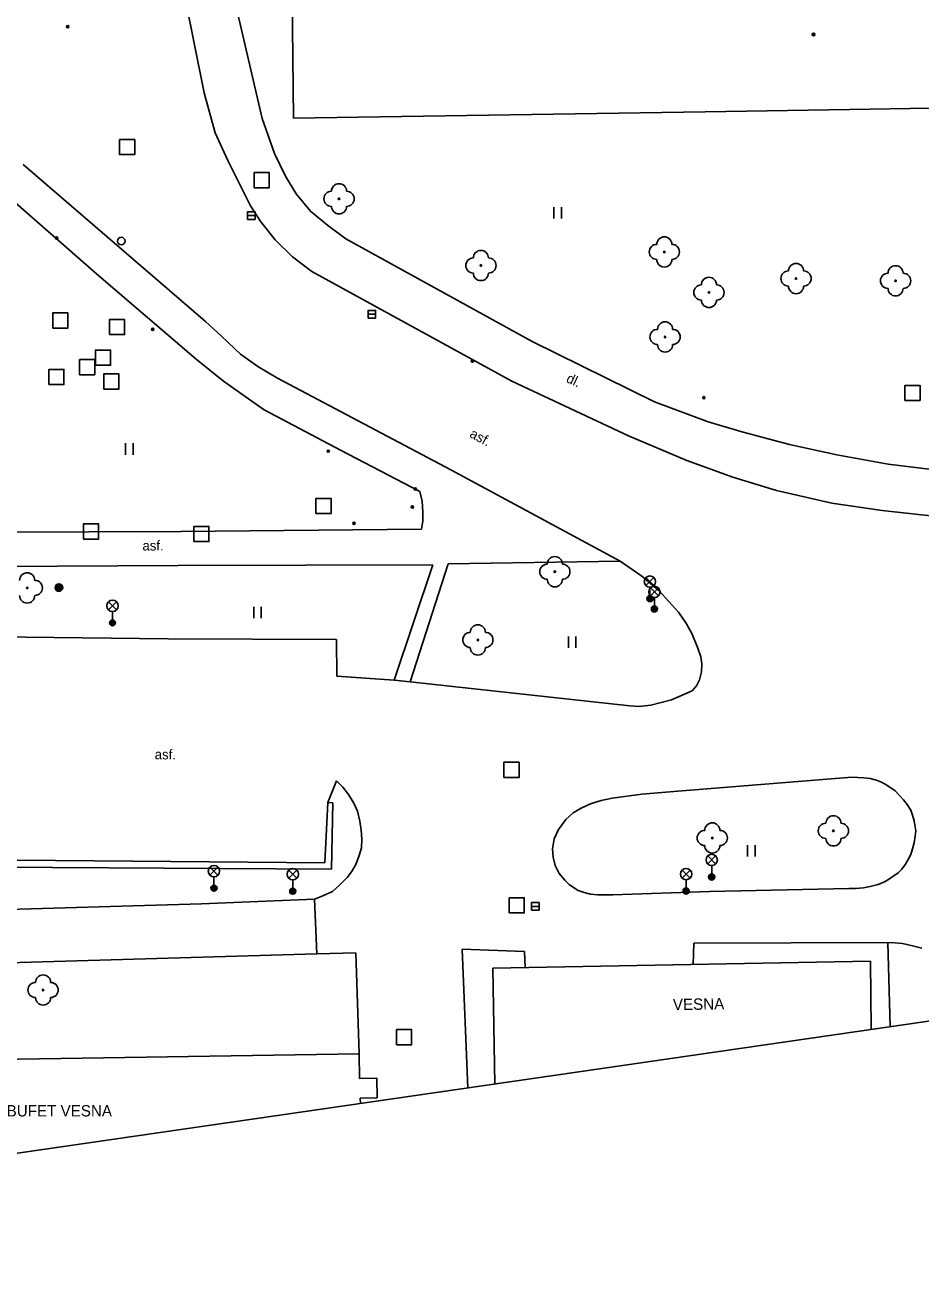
# Model space of a CAD drawing. Extents: x -641829 to -641525, y -1114855 to -1114359.
# Drawn here: x -641632.1 to -641572.8, y -1114854.7 to -1114772 of the extents above; entities that cross this region are included whole.
import ezdxf

# ---------------------------------------------------------------- set-up
doc = ezdxf.new("R2010")
doc.units = 0
for name, color, linetype in [('Vrstva 1', 7, 'Continuous'), ('Vrstva 10', 7, 'Continuous'), ('Vrstva 11', 7, 'Continuous'), ('Vrstva 20', 7, 'Continuous'), ('Vrstva 22', 7, 'Continuous'), ('Vrstva 25', 7, 'Continuous'), ('Vrstva 26', 7, 'Continuous'), ('Vrstva 27', 7, 'Continuous'), ('Vrstva 28', 7, 'Continuous'), ('Vrstva 33', 7, 'Continuous'), ('Vrstva 36', 7, 'Continuous'), ('Vrstva 39', 7, 'Continuous'), ('Vrstva 40', 7, 'Continuous'), ('Vrstva 41', 7, 'Continuous'), ('Vrstva 5', 7, 'Continuous')]:
    doc.layers.add(name, color=color, linetype=linetype)

msp = doc.modelspace()

# ---------------------------------------------------------------- linework, layer by layer
at = {"layer": 'Vrstva 1'}
msp.add_line((-641689.21, -1114854.71), (-641533.66, -1114832.21), dxfattribs=at)
at = {"layer": 'Vrstva 10'}
for p, q in [((-641621.81, -1114768.5), (-641620.22, -1114776.44)), ((-641620.22, -1114776.44), (-641619.48, -1114779.08)), ((-641619.48, -1114779.08), (-641618.65, -1114780.9)), ((-641632.18, -1114781.17), (-641620.12, -1114791.56)), ((-641618.65, -1114780.9), (-641617.15, -1114783.91)), ((-641617.15, -1114783.91), (-641616.47, -1114784.97)), ((-641616.47, -1114784.97), (-641615.51, -1114786.15)), ((-641615.51, -1114786.15), (-641614.36, -1114787.27)), ((-641614.36, -1114787.27), (-641613.09, -1114788.24)), ((-641613.09, -1114788.24), (-641599.87, -1114795.5)), ((-641620.12, -1114791.56), (-641619.04, -1114792.55)), ((-641619.04, -1114792.55), (-641617.81, -1114793.71)), ((-641617.81, -1114793.71), (-641616.66, -1114794.53)), ((-641616.66, -1114794.53), (-641615.36, -1114795.29)), ((-641603.9, -1114801.36), (-641615.36, -1114795.29)), ((-641599.87, -1114795.5), (-641592.15, -1114799.11)), ((-641592.15, -1114799.11), (-641588.29, -1114800.74)), ((-641592.71, -1114807.4), (-641603.9, -1114801.36)), ((-641588.29, -1114800.74), (-641585.25, -1114801.84)), ((-641585.25, -1114801.84), (-641582.37, -1114802.73)), ((-641582.37, -1114802.73), (-641578.7, -1114803.55)), ((-641578.7, -1114803.55), (-641575.38, -1114804.04)), ((-641575.38, -1114804.04), (-641571.75, -1114804.44)), ((-641591.27, -1114808.39), (-641592.71, -1114807.4)), ((-641590.12, -1114809.36), (-641591.27, -1114808.39)), ((-641588.84, -1114810.76), (-641590.12, -1114809.36)), ((-641588.32, -1114811.54), (-641588.84, -1114810.76)), ((-641587.93, -1114812.22), (-641588.32, -1114811.54)), ((-641637.17, -1114812.37), (-641622.59, -1114812.52)), ((-641622.59, -1114812.52), (-641611.46, -1114812.58)), ((-641611.46, -1114812.58), (-641611.44, -1114814.99)), ((-641587.56, -1114813.15), (-641587.93, -1114812.22)), ((-641587.37, -1114813.71), (-641587.56, -1114813.15)), ((-641587.29, -1114814.19), (-641587.37, -1114813.71)), ((-641587.33, -1114814.71), (-641587.29, -1114814.19)), ((-641607.65, -1114815.27), (-641611.44, -1114814.99)), ((-641607.65, -1114815.27), (-641606.58, -1114815.36)), ((-641606.58, -1114815.36), (-641592.07, -1114816.96)), ((-641587.66, -1114815.64), (-641587.45, -1114815.23)), ((-641587.45, -1114815.23), (-641587.33, -1114814.71)), ((-641589.31, -1114816.55), (-641587.95, -1114815.96)), ((-641587.95, -1114815.96), (-641587.66, -1114815.64)), ((-641592.07, -1114816.96), (-641591.46, -1114816.99)), ((-641591.46, -1114816.99), (-641590.67, -1114816.91)), ((-641590.67, -1114816.91), (-641589.99, -1114816.74)), ((-641589.99, -1114816.74), (-641589.31, -1114816.55)), ((-641612.04, -1114823.35), (-641611.45, -1114821.91)), ((-641611.45, -1114821.91), (-641611.05, -1114822.34)), ((-641589.15, -1114822.62), (-641577.38, -1114821.68)), ((-641577.38, -1114821.68), (-641576.58, -1114821.71)), ((-641576.58, -1114821.71), (-641576.16, -1114821.77)), ((-641576.16, -1114821.77), (-641575.76, -1114821.87)), ((-641575.76, -1114821.87), (-641575.41, -1114822.01)), ((-641575.41, -1114822.01), (-641575.06, -1114822.19)), ((-641611.05, -1114822.34), (-641610.66, -1114822.82)), ((-641610.66, -1114822.82), (-641610.31, -1114823.4)), ((-641593.24, -1114823.05), (-641591.27, -1114822.79)), ((-641591.27, -1114822.79), (-641589.15, -1114822.62)), ((-641575.06, -1114822.19), (-641574.51, -1114822.58)), ((-641574.51, -1114822.58), (-641573.97, -1114823.18)), ((-641610.31, -1114823.4), (-641610.08, -1114823.92)), ((-641595.81, -1114824.02), (-641595.28, -1114823.72)), ((-641595.28, -1114823.72), (-641594.66, -1114823.44)), ((-641594.66, -1114823.44), (-641593.96, -1114823.22)), ((-641593.96, -1114823.22), (-641593.24, -1114823.05)), ((-641573.97, -1114823.18), (-641573.72, -1114823.48)), ((-641573.72, -1114823.48), (-641573.49, -1114823.86)), ((-641610.08, -1114823.92), (-641609.91, -1114824.59)), ((-641609.91, -1114824.59), (-641609.83, -1114825.17)), ((-641596.78, -1114825.13), (-641596.29, -1114824.48)), ((-641596.29, -1114824.48), (-641595.81, -1114824.02)), ((-641573.49, -1114823.86), (-641573.36, -1114824.19)), ((-641573.36, -1114824.19), (-641573.25, -1114824.56)), ((-641573.25, -1114824.56), (-641573.16, -1114825.23)), ((-641609.83, -1114825.17), (-641609.79, -1114825.77)), ((-641597.06, -1114825.75), (-641596.78, -1114825.13)), ((-641573.16, -1114825.23), (-641573.19, -1114825.58)), ((-641609.79, -1114825.77), (-641609.81, -1114826.34)), ((-641597.18, -1114826.41), (-641597.06, -1114825.75)), ((-641573.26, -1114826.01), (-641573.36, -1114826.41)), ((-641573.19, -1114825.58), (-641573.26, -1114826.01)), ((-641609.95, -1114826.85), (-641610.18, -1114827.44)), ((-641609.81, -1114826.34), (-641609.95, -1114826.85)), ((-641597.18, -1114826.41), (-641597.13, -1114826.95)), ((-641597.13, -1114826.95), (-641596.99, -1114827.51)), ((-641573.64, -1114827.07), (-641573.84, -1114827.42)), ((-641573.49, -1114826.78), (-641573.64, -1114827.07)), ((-641573.36, -1114826.41), (-641573.49, -1114826.78)), ((-641610.47, -1114827.92), (-641610.76, -1114828.31)), ((-641610.18, -1114827.44), (-641610.47, -1114827.92)), ((-641596.99, -1114827.51), (-641596.74, -1114828.03)), ((-641574.08, -1114827.75), (-641574.32, -1114827.99)), ((-641573.84, -1114827.42), (-641574.08, -1114827.75)), ((-641610.76, -1114828.31), (-641611.25, -1114828.82)), ((-641596.74, -1114828.03), (-641596.36, -1114828.49)), ((-641596.07, -1114828.76), (-641596.36, -1114828.49)), ((-641595.78, -1114828.97), (-641596.07, -1114828.76)), ((-641575.23, -1114828.59), (-641575.65, -1114828.77)), ((-641574.9, -1114828.4), (-641575.23, -1114828.59)), ((-641574.32, -1114827.99), (-641574.9, -1114828.4)), ((-641612.36, -1114829.52), (-641612.91, -1114829.73)), ((-641611.72, -1114829.22), (-641612.36, -1114829.52)), ((-641611.25, -1114828.82), (-641611.72, -1114829.22)), ((-641595.47, -1114829.16), (-641595.78, -1114828.97)), ((-641595.09, -1114829.3), (-641595.47, -1114829.16)), ((-641594.66, -1114829.41), (-641595.09, -1114829.3)), ((-641594.2, -1114829.45), (-641594.66, -1114829.41)), ((-641593.18, -1114829.46), (-641594.2, -1114829.45)), ((-641586.77, -1114829.24), (-641593.18, -1114829.46)), ((-641577.59, -1114829.04), (-641586.77, -1114829.24)), ((-641577.14, -1114829.03), (-641577.59, -1114829.04)), ((-641576.62, -1114828.98), (-641577.14, -1114829.03)), ((-641576.16, -1114828.9), (-641576.62, -1114828.98)), ((-641575.65, -1114828.77), (-641576.16, -1114828.9)), ((-641612.75, -1114833.36), (-641612.91, -1114829.73)), ((-641575.01, -1114832.61), (-641574.54, -1114832.62)), ((-641574.54, -1114832.62), (-641574.03, -1114832.67)), ((-641574.03, -1114832.67), (-641573.38, -1114832.81)), ((-641573.38, -1114832.81), (-641572.75, -1114832.98)), ((-641612.75, -1114833.36), (-641610.17, -1114833.29)), ((-641610.17, -1114833.29), (-641609.97, -1114839.96)), ((-641602.782, -1114842.208), (-641603.14, -1114833.04)), ((-641603.14, -1114833.04), (-641599.03, -1114833.19)), ((-641599.03, -1114833.19), (-641598.99, -1114834.26))]:
    msp.add_line(p, q, dxfattribs=at)
at = {"layer": 'Vrstva 11'}
for p, q in [((-641616.38, -1114778.12), (-641618.71, -1114768.03)), ((-641615.55, -1114780.44), (-641616.38, -1114778.12)), ((-641614.83, -1114781.94), (-641615.55, -1114780.44)), ((-641634.75, -1114781.92), (-641627.17, -1114788.53)), ((-641614.13, -1114783.1), (-641614.83, -1114781.94)), ((-641613.17, -1114784.25), (-641614.13, -1114783.1)), ((-641612.06, -1114785.18), (-641613.17, -1114784.25)), ((-641610.84, -1114786.08), (-641612.06, -1114785.18)), ((-641598.52, -1114792.88), (-641610.84, -1114786.08)), ((-641627.17, -1114788.53), (-641620.73, -1114794.04)), ((-641590.42, -1114796.87), (-641598.52, -1114792.88)), ((-641620.73, -1114794.04), (-641618.92, -1114795.5)), ((-641618.92, -1114795.5), (-641617.5, -1114796.51)), ((-641617.5, -1114796.51), (-641616.24, -1114797.4)), ((-641586.89, -1114798.18), (-641590.42, -1114796.87)), ((-641616.24, -1114797.4), (-641611.19, -1114800.05)), ((-641584.57, -1114798.87), (-641586.89, -1114798.18)), ((-641581.5, -1114799.67), (-641584.57, -1114798.87)), ((-641578.37, -1114800.36), (-641581.5, -1114799.67)), ((-641611.19, -1114800.05), (-641605.95, -1114802.79)), ((-641574.98, -1114800.99), (-641578.37, -1114800.36)), ((-641571.18, -1114801.45), (-641574.98, -1114800.99)), ((-641605.95, -1114802.79), (-641605.79, -1114803.43)), ((-641605.79, -1114803.43), (-641605.74, -1114804.15)), ((-641605.76, -1114804.75), (-641605.83, -1114805.28)), ((-641605.74, -1114804.15), (-641605.76, -1114804.75)), ((-641621.75, -1114805.43), (-641634.53, -1114805.48)), ((-641605.83, -1114805.28), (-641621.75, -1114805.43)), ((-641621.92, -1114807.67), (-641634.02, -1114807.75)), ((-641605.09, -1114807.63), (-641621.92, -1114807.67)), ((-641607.65, -1114815.27), (-641605.09, -1114807.63)), ((-641604.08, -1114807.57), (-641606.58, -1114815.36)), ((-641604.08, -1114807.57), (-641592.71, -1114807.4)), ((-641612.23, -1114827.33), (-641612.04, -1114823.35)), ((-641612.04, -1114823.35), (-641611.71, -1114823.36)), ((-641611.8, -1114827.76), (-641611.71, -1114823.36)), ((-641637.68, -1114827.61), (-641611.8, -1114827.76)), ((-641637.5, -1114830.54), (-641620.39, -1114830.05)), ((-641620.39, -1114830.05), (-641612.91, -1114829.73)), ((-641587.84, -1114832.65), (-641587.88, -1114834.06)), ((-641575.01, -1114832.61), (-641587.84, -1114832.65)), ((-641574.846, -1114838.167), (-641575.01, -1114832.61)), ((-641612.75, -1114833.36), (-641634.7, -1114833.98))]:
    msp.add_line(p, q, dxfattribs=at)
msp.add_lwpolyline([(-641612.23, -1114827.33), (-641637.68, -1114827.12)], dxfattribs=at)
at = {"layer": 'Vrstva 20'}
for centre, radius in [((-641629.23, -1114772.06), 0.075), ((-641629.23, -1114772.06), 0.0204), ((-641629.97, -1114786.03), 0.075), ((-641629.97, -1114786.03), 0.0204), ((-641623.61, -1114792.07), 0.075), ((-641623.61, -1114792.07), 0.0204), ((-641602.47, -1114794.17), 0.075), ((-641602.47, -1114794.17), 0.0204), ((-641587.17, -1114796.58), 0.075), ((-641587.17, -1114796.58), 0.0204), ((-641612, -1114800.12), 0.075), ((-641612, -1114800.12), 0.0204), ((-641606.25, -1114802.62), 0.075), ((-641606.25, -1114802.62), 0.0204), ((-641606.44, -1114803.81), 0.075), ((-641606.44, -1114803.81), 0.0204), ((-641610.3, -1114804.89), 0.075), ((-641610.3, -1114804.89), 0.0204)]:
    msp.add_circle(centre, radius, dxfattribs=at)
at = {"layer": 'Vrstva 22'}
for centre in [(-641611.29, -1114783.44), (-641589.78, -1114786.95), (-641601.91, -1114787.85), (-641581.07, -1114788.71), (-641574.49, -1114788.86), (-641586.83, -1114789.63), (-641589.73, -1114792.57), (-641597.02, -1114808.09), (-641631.91, -1114809.16), (-641602.11, -1114812.6), (-641578.6, -1114825.22), (-641586.61, -1114825.69), (-641630.86, -1114835.74)]:
    msp.add_circle(centre, 0.05, dxfattribs=at)
for centre, start, end in [((-641611.79, -1114783.44), 90, 270), ((-641611.29, -1114782.94), 0, 180), ((-641610.79, -1114783.44), 270, 90), ((-641611.29, -1114783.94), 180, 0), ((-641590.28, -1114786.95), 90, 270), ((-641589.78, -1114786.45), 0, 180), ((-641589.28, -1114786.95), 270, 90), ((-641602.41, -1114787.85), 90, 270), ((-641601.91, -1114787.35), 0, 180), ((-641601.41, -1114787.85), 270, 90), ((-641589.78, -1114787.45), 180, 0), ((-641581.57, -1114788.71), 90, 270), ((-641581.07, -1114788.21), 0, 180), ((-641580.57, -1114788.71), 270, 90), ((-641574.49, -1114788.36), 0, 180), ((-641601.91, -1114788.35), 180, 0), ((-641586.83, -1114789.13), 0, 180), ((-641574.99, -1114788.86), 90, 270), ((-641573.99, -1114788.86), 270, 90), ((-641587.33, -1114789.63), 90, 270), ((-641586.33, -1114789.63), 270, 90), ((-641581.07, -1114789.21), 180, 0), ((-641574.49, -1114789.36), 180, 0), ((-641586.83, -1114790.13), 180, 0), ((-641590.23, -1114792.57), 90, 270), ((-641589.73, -1114792.07), 0, 180), ((-641589.23, -1114792.57), 270, 90), ((-641589.73, -1114793.07), 180, 0), ((-641597.02, -1114807.59), 0, 180), ((-641597.52, -1114808.09), 90, 270), ((-641596.52, -1114808.09), 270, 90), ((-641631.91, -1114808.66), 0, 180), ((-641631.41, -1114809.16), 270, 90), ((-641597.02, -1114808.59), 180, 0), ((-641631.91, -1114809.66), 180, 0), ((-641602.61, -1114812.6), 90, 270), ((-641602.11, -1114812.1), 0, 180), ((-641601.61, -1114812.6), 270, 90), ((-641602.11, -1114813.1), 180, 0), ((-641578.6, -1114824.72), 0, 180), ((-641587.11, -1114825.69), 90, 270), ((-641586.61, -1114825.19), 0, 180), ((-641586.11, -1114825.69), 270, 90), ((-641579.1, -1114825.22), 90, 270), ((-641578.1, -1114825.22), 270, 90), ((-641586.61, -1114826.19), 180, 0), ((-641578.6, -1114825.72), 180, 0), ((-641631.36, -1114835.74), 90, 270), ((-641630.86, -1114835.24), 0, 180), ((-641630.36, -1114835.74), 270, 90), ((-641630.86, -1114836.24), 180, 0)]:
    msp.add_arc(centre, 0.5, start, end, dxfattribs=at)
at = {"layer": 'Vrstva 25'}
for radius in [0.25, 0.2, 0.15, 0.1, 0.05]:
    msp.add_circle((-641629.81, -1114809.14), radius, dxfattribs=at)
at = {"layer": 'Vrstva 26'}
for points in [[(-641624.8, -1114779.52), (-641625.8, -1114779.52), (-641625.8, -1114780.52), (-641624.8, -1114780.52)], [(-641616.91, -1114782.71), (-641615.91, -1114782.71), (-641615.91, -1114781.71), (-641616.91, -1114781.71)], [(-641630.22, -1114791.98), (-641629.22, -1114791.98), (-641629.22, -1114790.98), (-641630.22, -1114790.98)], [(-641626.47, -1114792.42), (-641625.47, -1114792.42), (-641625.47, -1114791.42), (-641626.47, -1114791.42)], [(-641627.4, -1114794.44), (-641626.4, -1114794.44), (-641626.4, -1114793.44), (-641627.4, -1114793.44)], [(-641630.48, -1114795.72), (-641629.48, -1114795.72), (-641629.48, -1114794.72), (-641630.48, -1114794.72)], [(-641628.45, -1114795.07), (-641627.45, -1114795.07), (-641627.45, -1114794.07), (-641628.45, -1114794.07)], [(-641626.85, -1114796.02), (-641625.85, -1114796.02), (-641625.85, -1114795.02), (-641626.85, -1114795.02)], [(-641573.87, -1114796.77), (-641572.87, -1114796.77), (-641572.87, -1114795.77), (-641573.87, -1114795.77)], [(-641612.82, -1114804.25), (-641611.82, -1114804.25), (-641611.82, -1114803.25), (-641612.82, -1114803.25)], [(-641628.19, -1114805.93), (-641627.19, -1114805.93), (-641627.19, -1114804.93), (-641628.19, -1114804.93)], [(-641620.89, -1114806.1), (-641619.89, -1114806.1), (-641619.89, -1114805.1), (-641620.89, -1114805.1)], [(-641600.39, -1114821.69), (-641599.39, -1114821.69), (-641599.39, -1114820.69), (-641600.39, -1114820.69)], [(-641600.04, -1114830.64), (-641599.04, -1114830.64), (-641599.04, -1114829.64), (-641600.04, -1114829.64)], [(-641607.49, -1114839.36), (-641606.49, -1114839.36), (-641606.49, -1114838.36), (-641607.49, -1114838.36)]]:
    msp.add_lwpolyline(points, close=True, dxfattribs=at)
at = {"layer": 'Vrstva 27'}
for p, q in [((-641617.34, -1114784.55), (-641616.84, -1114784.55)), ((-641609.37, -1114791.07), (-641608.87, -1114791.07)), ((-641598.56, -1114830.21), (-641598.06, -1114830.21))]:
    msp.add_line(p, q, dxfattribs=at)
for points in [[(-641617.34, -1114784.8), (-641616.84, -1114784.8), (-641616.84, -1114784.3), (-641617.34, -1114784.3)], [(-641609.37, -1114791.32), (-641608.87, -1114791.32), (-641608.87, -1114790.82), (-641609.37, -1114790.82)], [(-641598.56, -1114830.46), (-641598.06, -1114830.46), (-641598.06, -1114829.96), (-641598.56, -1114829.96)]]:
    msp.add_lwpolyline(points, close=True, dxfattribs=at)
at = {"layer": 'Vrstva 28'}
msp.add_circle((-641625.69, -1114786.23), 0.25, dxfattribs=at)
at = {"layer": 'Vrstva 33'}
for p, q in [((-641590.994, -1114809.01), (-641590.466, -1114808.48)), ((-641590.994, -1114808.48), (-641590.466, -1114809.01)), ((-641590.73, -1114809.12), (-641590.73, -1114809.87)), ((-641590.704, -1114809.69), (-641590.176, -1114809.16)), ((-641590.704, -1114809.16), (-641590.176, -1114809.69)), ((-641626.534, -1114810.61), (-641626.006, -1114810.08)), ((-641626.534, -1114810.08), (-641626.006, -1114810.61)), ((-641590.44, -1114809.8), (-641590.44, -1114810.55)), ((-641626.27, -1114810.72), (-641626.27, -1114811.47)), ((-641586.914, -1114827.41), (-641586.386, -1114826.88)), ((-641586.914, -1114826.88), (-641586.386, -1114827.41)), ((-641619.824, -1114828.15), (-641619.296, -1114827.62)), ((-641619.824, -1114827.62), (-641619.296, -1114828.15)), ((-641614.614, -1114828.35), (-641614.086, -1114827.82)), ((-641614.614, -1114827.82), (-641614.086, -1114828.35)), ((-641588.604, -1114828.34), (-641588.076, -1114827.81)), ((-641588.604, -1114827.81), (-641588.076, -1114828.34)), ((-641586.65, -1114827.52), (-641586.65, -1114828.27)), ((-641619.56, -1114828.26), (-641619.56, -1114829.01)), ((-641614.35, -1114828.46), (-641614.35, -1114829.21)), ((-641588.34, -1114828.45), (-641588.34, -1114829.2))]:
    msp.add_line(p, q, dxfattribs=at)
for centre, radius in [((-641590.73, -1114808.745), 0.375), ((-641590.73, -1114809.87), 0.2), ((-641590.73, -1114809.87), 0.145), ((-641590.44, -1114809.425), 0.375), ((-641626.27, -1114810.345), 0.375), ((-641590.73, -1114809.87), 0.0876), ((-641590.44, -1114810.55), 0.2), ((-641590.44, -1114810.55), 0.145), ((-641590.44, -1114810.55), 0.0876), ((-641626.27, -1114811.47), 0.2), ((-641626.27, -1114811.47), 0.145), ((-641626.27, -1114811.47), 0.0876), ((-641586.65, -1114827.145), 0.375), ((-641619.56, -1114827.885), 0.375), ((-641614.35, -1114828.085), 0.375), ((-641588.34, -1114828.075), 0.375), ((-641586.65, -1114828.27), 0.2), ((-641586.65, -1114828.27), 0.145), ((-641586.65, -1114828.27), 0.0876), ((-641619.56, -1114829.01), 0.2), ((-641619.56, -1114829.01), 0.145), ((-641619.56, -1114829.01), 0.0876), ((-641614.35, -1114829.21), 0.2), ((-641614.35, -1114829.21), 0.145), ((-641614.35, -1114829.21), 0.0876), ((-641588.34, -1114829.2), 0.2), ((-641588.34, -1114829.2), 0.145), ((-641588.34, -1114829.2), 0.0876)]:
    msp.add_circle(centre, radius, dxfattribs=at)
at = {"layer": 'Vrstva 36'}
for p, q in [((-641597.084, -1114784.742), (-641597.084, -1114783.994)), ((-641596.584, -1114784.742), (-641596.584, -1114783.994)), ((-641625.414, -1114800.354), (-641625.414, -1114799.602)), ((-641624.914, -1114800.354), (-641624.914, -1114799.602)), ((-641616.934, -1114811.164), (-641616.934, -1114810.412)), ((-641616.434, -1114811.164), (-641616.434, -1114810.412)), ((-641596.124, -1114813.114), (-641596.124, -1114812.362)), ((-641595.624, -1114813.114), (-641595.624, -1114812.362)), ((-641584.284, -1114826.922), (-641584.284, -1114826.174)), ((-641583.784, -1114826.922), (-641583.784, -1114826.174))]:
    msp.add_line(p, q, dxfattribs=at)
at = {"layer": 'Vrstva 39'}
for radius in [0.09, 0.0398]:
    msp.add_circle((-641579.91, -1114772.58), radius, dxfattribs=at)
at = {"layer": 'Vrstva 5'}
for p, q in [((-641614.42, -1114767.57), (-641614.3, -1114778.1)), ((-641576.17, -1114777.51), (-641560.69, -1114777.23)), ((-641614.3, -1114778.1), (-641587.09, -1114777.69)), ((-641587.09, -1114777.69), (-641576.17, -1114777.51)), ((-641576.15, -1114833.84), (-641601.12, -1114834.3)), ((-641600.981, -1114841.948), (-641601.12, -1114834.3)), ((-641576.104, -1114838.349), (-641576.15, -1114833.84)), ((-641646.44, -1114840.53), (-641609.97, -1114839.96)), ((-641609.93, -1114841.6), (-641609.97, -1114839.96)), ((-641609.93, -1114841.6), (-641608.8, -1114841.57)), ((-641608.8, -1114841.57), (-641608.76, -1114842.86)), ((-641609.89, -1114842.89), (-641608.76, -1114842.86)), ((-641609.881, -1114843.235), (-641609.89, -1114842.89))]:
    msp.add_line(p, q, dxfattribs=at)

# ---------------------------------------------------------------- texts
at = {"layer": 'Vrstva 40'}
for s, height, rotation, p in [('dl.', 0.65, 334.92625, (-641596.32, -1114795.53)), ('asf.', 0.6499, 331.64126, (-641602.71, -1114799.16)), ('asf.', 0.65, 0.20174, (-641624.29, -1114806.69)), ('asf.', 0.6499, 359.41056, (-641623.48, -1114820.49))]:
    msp.add_text(s, height=height, rotation=rotation, dxfattribs=at).set_placement(p)
at = {"layer": 'Vrstva 41'}
msp.add_text('VESNA', height=0.7499, rotation=1.05539, dxfattribs=at).set_placement((-641589.21, -1114837.08))
msp.add_text('BUFET VESNA', height=0.75, dxfattribs=at).set_placement((-641633.27, -1114844.1))

doc.saveas('drawing.dxf')
